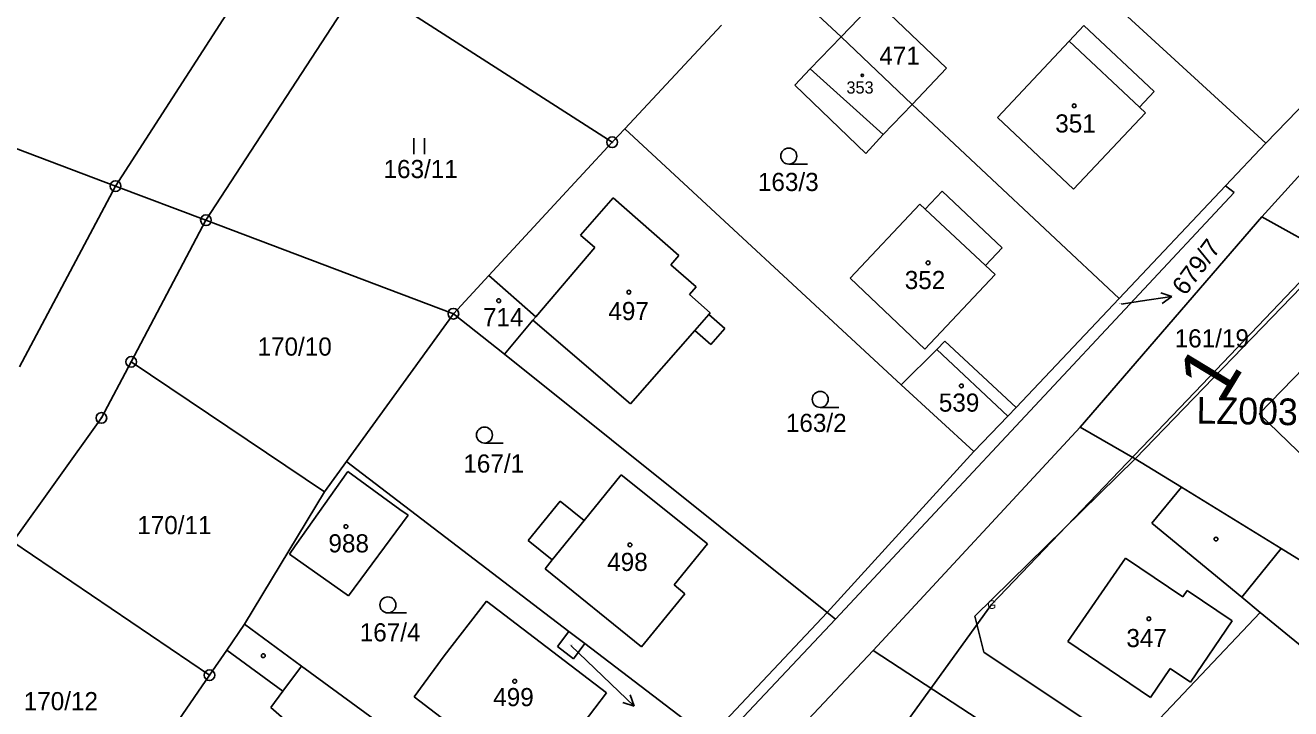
# Model space of a CAD drawing. Extents: x -738131 to -734179, y -1033447 to -1030078.
# Drawn here: x -736449.3 to -736330.8, y -1032472.6 to -1032408.5 of the extents above; entities that cross this region are included whole.
import ezdxf

# ---------------------------------------------------------------- set-up
doc = ezdxf.new("R2010")
doc.units = 0
for name, color, linetype in [('ftf_2050', 7, 'Continuous'), ('ftf_3010', 7, 'Continuous'), ('ftf_3010_ftf_3010_gtda_3015_gtda_3015_1', 7, 'Continuous'), ('ftf_3240', 7, 'Continuous'), ('Vrstva 1', 7, 'Continuous'), ('Vrstva 2', 7, 'Continuous'), ('Vrstva 3', 7, 'Continuous'), ('Vrstva 4', 7, 'Continuous'), ('Vrstva 5', 7, 'Continuous'), ('Vrstva 7', 7, 'Continuous'), ('Vrstva 8', 7, 'Continuous')]:
    doc.layers.add(name, color=color, linetype=linetype)

msp = doc.modelspace()

# ---------------------------------------------------------------- linework, layer by layer
at = {"layer": 'ftf_2050'}
for points in [[(-736314.93, -1032416.87), (-736339.09, -1032442.19)], [(-736339.09, -1032442.19), (-736358.79, -1032462.83), (-736370.66, -1032479.27)]]:
    msp.add_lwpolyline(points, dxfattribs=at)
at = {"layer": 'Vrstva 1'}
for points in [[(-736333.1, -1032419.6), (-736366.06, -1032389.34)], [(-736427.3, -1032402.64), (-736440.81, -1032423.61)], [(-736379.38, -1032403.56), (-736372.87, -1032409.63)], [(-736417.8, -1032404.42), (-736432.35, -1032426.81)], [(-736417.8, -1032404.42), (-736394.31, -1032419.5)], [(-736319.23, -1032405.23), (-736333.1, -1032419.6)], [(-736372.87, -1032409.63), (-736369.63, -1032406.24)], [(-736369.63, -1032406.24), (-736363.01, -1032412.56)], [(-736393.14, -1032418.24), (-736384.07, -1032408.52)], [(-736372.87, -1032409.63), (-736375.78, -1032412.62)], [(-736366.24, -1032415.95), (-736372.87, -1032409.63)], [(-736350.16, -1032408.56), (-736351.54, -1032410.03)], [(-736343.56, -1032414.75), (-736350.16, -1032408.56)], [(-736358.25, -1032417.17), (-736351.54, -1032410.03)], [(-736440.81, -1032423.61), (-736470.84, -1032412.26)], [(-736375.78, -1032412.62), (-736377.2, -1032414.15)], [(-736363.01, -1032412.56), (-736366.24, -1032415.95)], [(-736377.2, -1032414.15), (-736370.58, -1032420.55)], [(-736344.94, -1032416.22), (-736343.56, -1032414.75)], [(-736368.94, -1032418.79), (-736366.24, -1032415.95)], [(-736366.24, -1032415.95), (-736346.86, -1032434.14)], [(-736344.39, -1032416.74), (-736351.12, -1032423.91)], [(-736344.94, -1032416.22), (-736344.39, -1032416.74)], [(-736358.25, -1032417.17), (-736351.12, -1032423.91)], [(-736333.5, -1032426.5), (-736325.22, -1032417.36)], [(-736394.31, -1032419.5), (-736393.14, -1032418.24)], [(-736393.14, -1032418.24), (-736367.25, -1032442.24)], [(-736370.58, -1032420.55), (-736368.94, -1032418.79)], [(-736394.31, -1032419.5), (-736399.75, -1032425.38)], [(-736336.88, -1032423.6), (-736333.1, -1032419.6)], [(-736449.79, -1032440.55), (-736440.81, -1032423.61)], [(-736440.81, -1032423.61), (-736432.35, -1032426.81)], [(-736346.86, -1032434.14), (-736336.88, -1032423.6)], [(-736336.88, -1032423.6), (-736336.09, -1032424.21)], [(-736394.22, -1032424.71), (-736397.27, -1032428.22)], [(-736394.22, -1032424.71), (-736388.06, -1032430.12)], [(-736373.41, -1032464.2), (-736336.09, -1032424.21)], [(-736365, -1032425.77), (-736363.43, -1032424.1)], [(-736363.43, -1032424.1), (-736357.81, -1032429.39)], [(-736399.75, -1032425.38), (-736405.86, -1032432)], [(-736372.02, -1032432.23), (-736365.51, -1032425.29)], [(-736365.51, -1032425.29), (-736365, -1032425.77)], [(-736432.35, -1032426.81), (-736439.35, -1032440.08)], [(-736432.35, -1032426.81), (-736409.18, -1032435.57)], [(-736350.49, -1032446.21), (-736333.5, -1032426.5)], [(-736326.95, -1032430.13), (-736333.5, -1032426.5)], [(-736397.27, -1032428.22), (-736395.94, -1032429.38)], [(-736401.47, -1032435.87), (-736395.94, -1032429.38)], [(-736357.81, -1032429.39), (-736359.37, -1032431.05)], [(-736388.06, -1032430.12), (-736388.82, -1032430.98)], [(-736388.82, -1032430.98), (-736386.45, -1032433.06)], [(-736409.18, -1032435.57), (-736405.86, -1032432)], [(-736401.47, -1032435.87), (-736405.86, -1032432)], [(-736365.04, -1032438.88), (-736358.46, -1032431.91)], [(-736359.37, -1032431.05), (-736358.46, -1032431.91)], [(-736327.97, -1032431.18), (-736345.34, -1032449.16)], [(-736386.45, -1032433.06), (-736387.08, -1032433.77)], [(-736372.02, -1032432.23), (-736365.04, -1032438.88)], [(-736387.08, -1032433.77), (-736385.13, -1032435.48)], [(-736346.86, -1032434.14), (-736356.5, -1032444.35)], [(-736409.18, -1032435.57), (-736419.19, -1032449.42)], [(-736409.18, -1032435.57), (-736404.4, -1032439.36)], [(-736385.13, -1032435.48), (-736385.26, -1032435.64)], [(-736385.26, -1032435.64), (-736383.76, -1032436.95)], [(-736404.4, -1032439.36), (-736401.73, -1032436.17)], [(-736401.73, -1032436.17), (-736401.47, -1032435.87)], [(-736401.73, -1032436.17), (-736392.61, -1032444.01)], [(-736386.58, -1032437.14), (-736392.61, -1032444.01)], [(-736385.07, -1032438.46), (-736386.58, -1032437.14)], [(-736383.76, -1032436.95), (-736385.07, -1032438.46)], [(-736367.25, -1032442.24), (-736363.93, -1032438.94)], [(-736363.93, -1032438.94), (-736363.16, -1032438.14)], [(-736363.16, -1032438.14), (-736356.5, -1032444.35)], [(-736327.4, -1032438.41), (-736333.74, -1032444.94)], [(-736442.14, -1032445.34), (-736439.35, -1032440.08)], [(-736439.35, -1032440.08), (-736421.25, -1032452.27)], [(-736374.19, -1032463.57), (-736404.4, -1032439.36)], [(-736367.25, -1032442.24), (-736360.44, -1032448.48)], [(-736357.27, -1032445.18), (-736360.44, -1032448.48)], [(-736356.5, -1032444.35), (-736357.27, -1032445.18)], [(-736333.74, -1032444.94), (-736326.52, -1032451.91)], [(-736450.42, -1032456.94), (-736442.14, -1032445.34)], [(-736369.87, -1032467.14), (-736350.49, -1032446.21)], [(-736345.34, -1032449.16), (-736350.49, -1032446.21)], [(-736374.19, -1032463.57), (-736360.44, -1032448.48)], [(-736421.25, -1032452.27), (-736419.19, -1032449.42)], [(-736418.74, -1032449.77), (-736419.19, -1032449.42)], [(-736398.37, -1032465.34), (-736418.74, -1032449.77)], [(-736360.36, -1032463.92), (-736345.34, -1032449.16)], [(-736341.02, -1032451.83), (-736345.34, -1032449.16)], [(-736424.01, -1032457.31), (-736419.06, -1032450.35)], [(-736419.06, -1032450.35), (-736414.18, -1032453.91)], [(-736393.46, -1032450.68), (-736396.93, -1032454.96)], [(-736393.46, -1032450.68), (-736385.39, -1032457.14)], [(-736421.25, -1032452.27), (-736428.74, -1032464.66)], [(-736341.02, -1032451.83), (-736331.69, -1032457.58)], [(-736399.18, -1032453.13), (-736402.18, -1032456.82)], [(-736396.93, -1032454.96), (-736399.18, -1032453.13)], [(-736413.43, -1032454.46), (-736419, -1032462)], [(-736414.18, -1032453.91), (-736413.43, -1032454.46)], [(-736450.42, -1032456.94), (-736432.02, -1032469.45)], [(-736402.18, -1032456.82), (-736399.93, -1032458.65)], [(-736424.52, -1032458.12), (-736424.01, -1032457.31)], [(-736419, -1032462), (-736424.52, -1032458.12)], [(-736385.39, -1032457.14), (-736388.52, -1032460.99)], [(-736323.23, -1032462.8), (-736331.69, -1032457.58)], [(-736400.59, -1032459.47), (-736399.93, -1032458.65)], [(-736391.56, -1032466.79), (-736400.59, -1032459.47)], [(-736387.51, -1032461.81), (-736391.56, -1032466.79)], [(-736388.52, -1032460.99), (-736387.51, -1032461.81)], [(-736410.04, -1032467.62), (-736406.07, -1032462.52)], [(-736406.07, -1032462.52), (-736394.85, -1032471.1)], [(-736374.19, -1032463.57), (-736385.26, -1032475.35)], [(-736373.41, -1032464.2), (-736374.19, -1032463.57)], [(-736359.52, -1032467.3), (-736360.36, -1032463.92)], [(-736333.63, -1032463.56), (-736345.81, -1032476.44)], [(-736322.01, -1032473.11), (-736333.63, -1032463.56)], [(-736430.4, -1032467.09), (-736428.74, -1032464.66)], [(-736423.39, -1032468.59), (-736428.74, -1032464.66)], [(-736373.41, -1032464.2), (-736417.58, -1032511.12)], [(-736399.44, -1032466.75), (-736398.37, -1032465.34)], [(-736398.37, -1032465.34), (-736396.86, -1032466.49)], [(-736396.86, -1032466.49), (-736397.94, -1032467.9)], [(-736396.86, -1032466.49), (-736385.26, -1032475.35)], [(-736432.02, -1032469.45), (-736430.4, -1032467.09)], [(-736425.16, -1032470.95), (-736430.4, -1032467.09)], [(-736369.87, -1032467.14), (-736414.12, -1032514.16)], [(-736412.85, -1032471.48), (-736410.04, -1032467.62)], [(-736397.94, -1032467.9), (-736399.44, -1032466.75)], [(-736334.7, -1032490.17), (-736369.87, -1032467.14)], [(-736345.81, -1032476.44), (-736359.52, -1032467.3)], [(-736423.39, -1032468.59), (-736414.91, -1032474.81)], [(-736432.02, -1032469.45), (-736441.04, -1032482.61)], [(-736426.28, -1032472.47), (-736425.16, -1032470.95)], [(-736394.85, -1032471.1), (-736397.03, -1032473.97)], [(-736422.74, -1032475.56), (-736426.28, -1032472.47)], [(-736408.32, -1032474.94), (-736412.85, -1032471.48)]]:
    msp.add_lwpolyline(points, dxfattribs=at)
at = {"layer": 'Vrstva 3'}
for p, q in [((-736412.9, -1032420.62), (-736412.9, -1032419.12)), ((-736411.9, -1032420.62), (-736411.9, -1032419.12)), ((-736377.78, -1032421.55), (-736376.03, -1032421.55)), ((-736374.83, -1032444.35), (-736373.08, -1032444.35)), ((-736406.27, -1032447.69), (-736404.52, -1032447.69)), ((-736415.31, -1032463.61), (-736413.56, -1032463.61))]:
    msp.add_line(p, q, dxfattribs=at)
for centre in [(-736377.78, -1032420.8), (-736374.83, -1032443.6), (-736406.27, -1032446.94), (-736415.31, -1032462.86)]:
    msp.add_circle(centre, 0.75, dxfattribs=at)
at = {"layer": 'Vrstva 4'}
for points in [[(-736351.54, -1032410.03), (-736344.94, -1032416.22)], [(-736375.78, -1032412.62), (-736368.94, -1032418.79)], [(-736365, -1032425.77), (-736359.37, -1032431.05)], [(-736386.58, -1032437.14), (-736385.26, -1032435.64)], [(-736363.93, -1032438.94), (-736357.27, -1032445.18)], [(-736341.02, -1032451.83), (-736343.79, -1032455.2)], [(-736399.93, -1032458.65), (-736396.93, -1032454.96)], [(-736335.35, -1032462.14), (-736343.79, -1032455.2)], [(-736335.35, -1032462.14), (-736331.69, -1032457.58)], [(-736346.24, -1032458.49), (-736351.66, -1032466.3)], [(-736346.24, -1032458.49), (-736340.89, -1032462.12)], [(-736340.89, -1032462.12), (-736340.47, -1032461.5)], [(-736340.47, -1032461.5), (-736336.28, -1032464.35)], [(-736333.63, -1032463.56), (-736335.35, -1032462.14)], [(-736336.28, -1032464.35), (-736340.17, -1032470.09)], [(-736351.66, -1032466.3), (-736343.9, -1032471.53)], [(-736423.39, -1032468.59), (-736425.16, -1032470.95)], [(-736342.06, -1032468.81), (-736343.9, -1032471.53)], [(-736340.17, -1032470.09), (-736342.06, -1032468.81)]]:
    msp.add_lwpolyline(points, dxfattribs=at)
at = {"layer": 'Vrstva 5'}
for centre, radius in [((-736370.9, -1032413.23), 0.117), ((-736351.05, -1032416.08), 0.175), ((-736364.74, -1032430.8), 0.175), ((-736392.75, -1032433.55), 0.175), ((-736404.94, -1032434.35), 0.175), ((-736361.62, -1032442.34), 0.175), ((-736419.24, -1032455.52), 0.175), ((-736392.65, -1032457.24), 0.175), ((-736337.78, -1032456.69), 0.175), ((-736344.06, -1032464.16), 0.175), ((-736426.98, -1032467.62), 0.175), ((-736403.44, -1032470.02), 0.175)]:
    msp.add_circle(centre, radius, dxfattribs=at)
at = {"layer": 'Vrstva 7'}
for p, q in [((-736344.87, -1032434.41), (-736341.9, -1032433.97)), ((-736341.9, -1032433.97), (-736342.96, -1032433.62)), ((-736341.9, -1032433.97), (-736342.82, -1032434.61)), ((-736394.43, -1032470.27), (-736392.27, -1032472.35)), ((-736392.27, -1032472.35), (-736393.33, -1032472.02)), ((-736392.27, -1032472.35), (-736392.64, -1032471.3))]:
    msp.add_line(p, q, dxfattribs=at)
for points in [[(-736346.62, -1032434.67), (-736344.87, -1032434.41)], [(-736398.2, -1032466.65), (-736394.43, -1032470.27)]]:
    msp.add_lwpolyline(points, dxfattribs=at)
at = {"layer": 'Vrstva 8'}
for centre, radius in [((-736394.31, -1032419.5), 0.5), ((-736394.31, -1032419.5), 0.0303), ((-736440.81, -1032423.61), 0.5), ((-736440.81, -1032423.61), 0.0303), ((-736432.35, -1032426.81), 0.5), ((-736432.35, -1032426.81), 0.0303), ((-736409.18, -1032435.57), 0.5), ((-736409.18, -1032435.57), 0.0303), ((-736439.35, -1032440.08), 0.5), ((-736439.35, -1032440.08), 0.0303), ((-736442.14, -1032445.34), 0.5), ((-736442.14, -1032445.34), 0.0303), ((-736432.02, -1032469.45), 0.5), ((-736432.02, -1032469.45), 0.0303)]:
    msp.add_circle(centre, radius, dxfattribs=at)

# ---------------------------------------------------------------- texts
at = {"layer": 'ftf_3010'}
msp.add_text('1', height=5.2, rotation=58.7481, dxfattribs=at).set_placement((-736337.21, -1032444.09))
at = {"layer": 'ftf_3010_ftf_3010_gtda_3015_gtda_3015_1'}
msp.add_text('LZ00378', height=2.5, rotation=358.9583, dxfattribs=at).set_placement((-736339.62, -1032445.86))
at = {"layer": 'ftf_3240'}
msp.add_text('G', height=0.8, dxfattribs=at).set_placement((-736359.19, -1032463.23))
at = {"layer": 'Vrstva 2'}
for s, height, p in [('471', 1.7, (-736369.3, -1032412.24)), ('353', 1.14, (-736372.38, -1032414.94)), ('351', 1.7, (-736352.83, -1032418.59)), ('163/11', 1.7, (-736415.72, -1032422.86)), ('163/3', 1.7, (-736380.67, -1032424.07)), ('352', 1.7, (-736366.92, -1032433.26)), ('497', 1.7, (-736394.67, -1032436.17)), ('714', 1.7, (-736406.41, -1032436.74)), ('679/7', 0.1, (-736346.8, -1032434.67)), ('170/10', 1.7, (-736427.52, -1032439.5)), ('161/19', 1.7, (-736341.65, -1032438.73)), ('539', 1.7, (-736363.73, -1032444.75)), ('163/2', 1.7, (-736378.05, -1032446.65)), ('167/1', 1.7, (-736408.25, -1032450.46)), ('170/11', 1.7, (-736438.78, -1032456.23)), ('988', 1.7, (-736420.88, -1032457.94)), ('498', 1.7, (-736394.78, -1032459.68)), ('167/4', 1.7, (-736417.95, -1032466.28)), ('347', 1.7, (-736346.17, -1032466.82)), ('167/5', 0.1, (-736398.36, -1032466.65)), ('170/12', 1.7, (-736449.41, -1032472.73)), ('499', 1.7, (-736405.45, -1032472.35))]:
    msp.add_text(s, height=height, dxfattribs=at).set_placement(p)
at = {"layer": 'Vrstva 7'}
msp.add_text('679/7', height=1.7, rotation=52.9893, dxfattribs=at).set_placement((-736340.67, -1032433.96))

doc.saveas('drawing.dxf')
